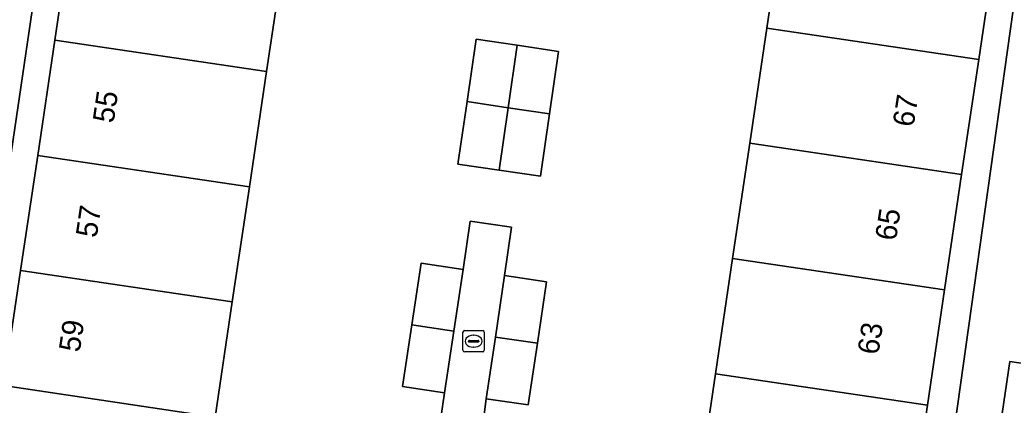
# Model space of a CAD drawing. Extents: x 164148 to 165261, y 382513 to 383432.
# Drawn here: x 164428.5 to 164475.24, y 383294.49 to 383312.65 of the extents above; entities that cross this region are included whole.
import ezdxf

# ---------------------------------------------------------------- set-up
doc = ezdxf.new("R2010")
doc.units = 0
for name, color, linetype in [('IMGEO_Erf', 7, 'Continuous'), ('IMGEO_Groenvoorziening', 7, 'Continuous'), ('IMGEO_Kolk', 7, 'Continuous'), ('IMGEO_Pand', 7, 'Continuous'), ('IMGEO_Pand_nummerreeks', 7, 'Continuous'), ('IMGEO_Voetpad_open', 7, 'Continuous')]:
    doc.layers.add(name, color=color, linetype=linetype)

msp = doc.modelspace()

# ---------------------------------------------------------------- linework, layer by layer
at = {"layer": 'IMGEO_Erf'}
for points in [[(164431.283, 383328.149), (164426.487, 383295.589), (164427.728, 383295.405), (164428.533, 383300.829), (164429.339, 383306.26), (164430.145, 383311.692), (164430.952, 383317.123), (164431.758, 383322.555), (164432.563, 383327.979)], [(164471.832, 383288.847), (164476.423, 383321.531), (164475.228, 383321.646), (164474.424, 383316.216), (164473.619, 383310.784), (164472.815, 383305.352), (164472.01, 383299.92), (164471.206, 383294.489), (164470.402, 383289.058)], [(164452.994, 383305.279), (164451.053, 383305.566), (164449.112, 383305.852), (164449.544, 383308.792), (164449.975, 383311.731), (164451.908, 383311.447), (164453.841, 383311.163), (164453.418, 383308.221)]]:
    msp.add_lwpolyline(points, close=True, dxfattribs=at)
for points in [[(164460.431, 383290.535), (164461.235, 383295.965), (164462.039, 383301.397), (164462.844, 383306.829), (164463.648, 383312.261), (164464.452, 383317.692)], [(164440.914, 383315.645), (164440.108, 383310.213), (164439.302, 383304.782), (164438.495, 383299.35), (164437.69, 383293.926)], [(164448.087, 383292.378), (164448.479, 383295.061), (164446.508, 383295.358), (164446.945, 383298.268), (164447.383, 383301.178), (164449.354, 383300.881), (164449.686, 383303.157), (164451.64, 383302.872), (164451.308, 383300.596), (164453.283, 383300.304), (164452.855, 383297.4), (164452.426, 383294.495), (164450.45, 383294.787), (164450.094, 383292.073)]]:
    msp.add_lwpolyline(points, dxfattribs=at)
at = {"layer": 'IMGEO_Groenvoorziening'}
msp.add_lwpolyline([(164473.903, 383288.541), (164478.567, 383287.854), (164479.745, 383295.856), (164475.081, 383296.543)], close=True, dxfattribs=at)
at = {"layer": 'IMGEO_Kolk'}
for p, q in [((164449.351, 383297.072), (164449.351, 383297.924)), ((164449.426, 383297.998), (164450.278, 383297.998)), ((164449.839, 383297.778), (164449.864, 383297.778)), ((164450.352, 383297.924), (164450.352, 383297.072)), ((164449.61, 383297.492), (164449.61, 383297.504)), ((164450.048, 383297.455), (164449.65, 383297.455)), ((164449.653, 383297.541), (164450.051, 383297.541)), ((164449.862, 383297.218), (164449.837, 383297.218)), ((164450.094, 383297.504), (164450.094, 383297.492)), ((164450.278, 383296.998), (164449.426, 383296.998))]:
    msp.add_line(p, q, dxfattribs=at)
for points in [[(164449.351, 383297.072), (164449.351, 383297.924)], [(164449.426, 383297.998), (164450.278, 383297.998)], [(164450.352, 383297.924), (164450.352, 383297.072)], [(164450.278, 383296.998), (164449.426, 383296.998)]]:
    msp.add_lwpolyline(points, dxfattribs=at)
for centre, radius, start, end in [((164449.428, 383297.922), 0.0765, 91.552, 178.448), ((164449.428, 383297.922), 0.0765, 91.552, 178.448), ((164450.276, 383297.922), 0.0765, 1.552, 88.448), ((164450.276, 383297.922), 0.0765, 1.552, 88.448), ((164449.65, 383297.501), 0.0403, 85.8775, 175.7526), ((164449.647, 383297.491), 0.0366, 178.938, 274.7102), ((164450.051, 383297.498), 0.043, 264.8664, 352.4533), ((164450.055, 383297.503), 0.0386, 1.7309, 96.639), ((164449.428, 383297.074), 0.0765, 181.552, 268.448), ((164449.428, 383297.074), 0.0765, 181.552, 268.448), ((164450.276, 383297.074), 0.0765, 271.552, 358.448), ((164450.276, 383297.074), 0.0765, 271.552, 358.448)]:
    msp.add_arc(centre, radius, start, end, dxfattribs=at)
for centre, major_axis, ratio, start_param, end_param in [((164449.838, 383297.498), (-0.387, 0.002), 0.722429, 4.712389, 7.853982), ((164449.863, 383297.498), (-0.39, 0.002), 0.717154, 1.570796, 4.712389)]:
    msp.add_ellipse(centre, major_axis=major_axis, ratio=ratio, start_param=start_param, end_param=end_param, dxfattribs=at)
at = {"layer": 'IMGEO_Pand'}
for points in [[(164463.648, 383312.261), (164473.619, 383310.784), (164474.424, 383316.216), (164464.452, 383317.692)], [(164440.914, 383315.645), (164430.952, 383317.123), (164430.145, 383311.692), (164440.108, 383310.213)], [(164472.815, 383305.352), (164473.619, 383310.784), (164463.648, 383312.261), (164462.844, 383306.829)], [(164440.108, 383310.213), (164430.145, 383311.692), (164429.339, 383306.26), (164439.302, 383304.782)], [(164449.544, 383308.792), (164451.481, 383308.506), (164451.908, 383311.447), (164449.975, 383311.731)], [(164451.481, 383308.506), (164453.418, 383308.221), (164453.841, 383311.163), (164451.908, 383311.447)], [(164451.053, 383305.566), (164451.481, 383308.506), (164449.544, 383308.792), (164449.112, 383305.852)], [(164451.053, 383305.566), (164452.994, 383305.279), (164453.418, 383308.221), (164451.481, 383308.506)], [(164472.815, 383305.352), (164462.844, 383306.829), (164462.039, 383301.397), (164472.01, 383299.92)], [(164438.495, 383299.35), (164439.302, 383304.782), (164429.339, 383306.26), (164428.533, 383300.829)], [(164472.01, 383299.92), (164462.039, 383301.397), (164461.235, 383295.965), (164471.206, 383294.489)], [(164438.495, 383299.35), (164428.533, 383300.829), (164427.728, 383295.405), (164437.69, 383293.926)], [(164446.945, 383298.268), (164448.916, 383297.971), (164449.354, 383300.881), (164447.383, 383301.178)], [(164452.855, 383297.4), (164453.283, 383300.304), (164451.308, 383300.596), (164450.879, 383297.692)], [(164446.945, 383298.268), (164446.508, 383295.358), (164448.479, 383295.061), (164448.916, 383297.971)], [(164452.855, 383297.4), (164450.879, 383297.692), (164450.45, 383294.787), (164452.426, 383294.495)], [(164461.235, 383295.965), (164460.431, 383290.535), (164470.402, 383289.058), (164471.206, 383294.489)]]:
    msp.add_lwpolyline(points, close=True, dxfattribs=at)
at = {"layer": 'IMGEO_Voetpad_open'}
msp.add_lwpolyline([(164482.088, 383287.337), (164480.794, 383287.477), (164478.567, 383287.854), (164473.903, 383288.541), (164471.832, 383288.847), (164470.402, 383289.058), (164460.431, 383290.535), (164450.094, 383292.073), (164448.087, 383292.378), (164437.69, 383293.926), (164427.728, 383295.405), (164426.487, 383295.589), (164424.202, 383296.082), (164419.654, 383296.689), (164417.275, 383296.961), (164416.031, 383297.135), (164406.075, 383298.606), (164395.714, 383300.146), (164393.743, 383300.442), (164383.343, 383301.97), (164373.371, 383303.448), (164372.113, 383303.598), (164376.956, 383336.181), (164376.85, 383338.67)], dxfattribs=at)
for points in [[(164431.283, 383328.149), (164428.965, 383328.467), (164427.799, 383320.419), (164423.209, 383321.084), (164424.375, 383329.132), (164422.097, 383329.482), (164417.275, 383296.961), (164419.654, 383296.689), (164420.722, 383304.694), (164425.27, 383304.087), (164424.202, 383296.082), (164426.487, 383295.589)], [(164485.646, 383320.108), (164483.388, 383320.434), (164482.221, 383312.401), (164477.54, 383313.081), (164478.707, 383321.114), (164476.423, 383321.531), (164471.832, 383288.847), (164473.903, 383288.541), (164475.081, 383296.543), (164479.745, 383295.856), (164478.567, 383287.854), (164480.794, 383287.477)], [(164450.879, 383297.692), (164451.308, 383300.596), (164451.64, 383302.872), (164449.686, 383303.157), (164449.354, 383300.881), (164448.916, 383297.971), (164448.479, 383295.061), (164448.087, 383292.378), (164450.094, 383292.073), (164450.45, 383294.787)]]:
    msp.add_lwpolyline(points, close=True, dxfattribs=at)

# ---------------------------------------------------------------- texts
at = {"layer": 'IMGEO_Pand_nummerreeks'}
for s, rotation, p in [('55', 81.6025, (164432.91, 383307.749)), ('67', 81.234, (164470.55, 383307.564)), ('57', 81.6025, (164432.112, 383302.346)), ('65', 81.234, (164469.723, 383302.203)), ('59', 81.6025, (164431.315, 383296.951)), ('63', 81.234, (164468.894, 383296.828))]:
    msp.add_text(s, height=1, rotation=rotation, dxfattribs=at).set_placement(p)

doc.saveas('drawing.dxf')
